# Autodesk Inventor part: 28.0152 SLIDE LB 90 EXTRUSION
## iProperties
Created: 2007-06
Part Number: 28.0152 SLIDE LB 90 EXTRUSION
Document SubType Name: Modeling
Designer: Andy Moles
Material: Aluminum-6061
Mass: 691.965 g
Surface Area: 1358.03 cm^2
Volume: 255.338 cm^3
Density: 2.71 g/cm^3
Author: Andy Moles
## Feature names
1. Extrusion1
2. Extrusion2
